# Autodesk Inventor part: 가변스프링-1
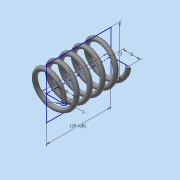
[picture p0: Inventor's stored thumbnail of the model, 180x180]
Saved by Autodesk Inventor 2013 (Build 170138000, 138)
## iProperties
Created: 2018-10
Part Number: 가변스프링-1
Material: 일반
Document SubType Name: Modeling
Designer: Administrator
Density: 1 g/cm^3
Mass: 0.780259 g
Surface Area: 15.7852 cm^2
Volume: 0.780259 cm^3
Author: Administrator
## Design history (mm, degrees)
sketch "스케치1"
  geometry: L1 (0, 0)-(0, 29.428); L2 (0, 0)-(8, 0); L3 (0, 29.428)-(8, 29.428); C1 r 1 at (8, 0)
  constraints: 6 end point, 1 centre point, 1 coincident, 1 parallel, 1 perpendicular, 1 vertical
  dimensions: "d0" = 29.42836 distance of L1.start L1.end (derived); "d1" = 8 distance of L1.start L2.end; "d2" = 8 distance of L1.end L3.end; "d3" = 2 diameter of C1
feature "코일1" sketch "스케치1" pitch "d4" = 10; turns "d6" = 5; dims "d5" = 29.42836 (= d0), "d7" = 0, angle "d8" = 90 deg, angle "d9" = 90 deg, "d10" = 0, "d11" = 0
sketch "스케치2"
  geometry: L1 (29.428, 11.5)-(0, 11.5); L2 (0, 11.5)-(0, -11.5); L3 (0, -11.5)-(29.428, -11.5); L4 (29.428, -11.5)-(29.428, 11.5); 2 further points
  constraints: 8 end point, 2 parallel, 1 coincident, 1 horizontal, 1 midpoint, 1 perpendicular
  dimensions: "d12" = 29.42836 distance between parallel lines of L2 L4 (derived); "d14" = 23 distance between parallel lines of L1 L3
extrude "돌출1" sketch "스케치2" stored distance "d15" = 0; taper "d16" = 0 deg
node "솔리드1"
